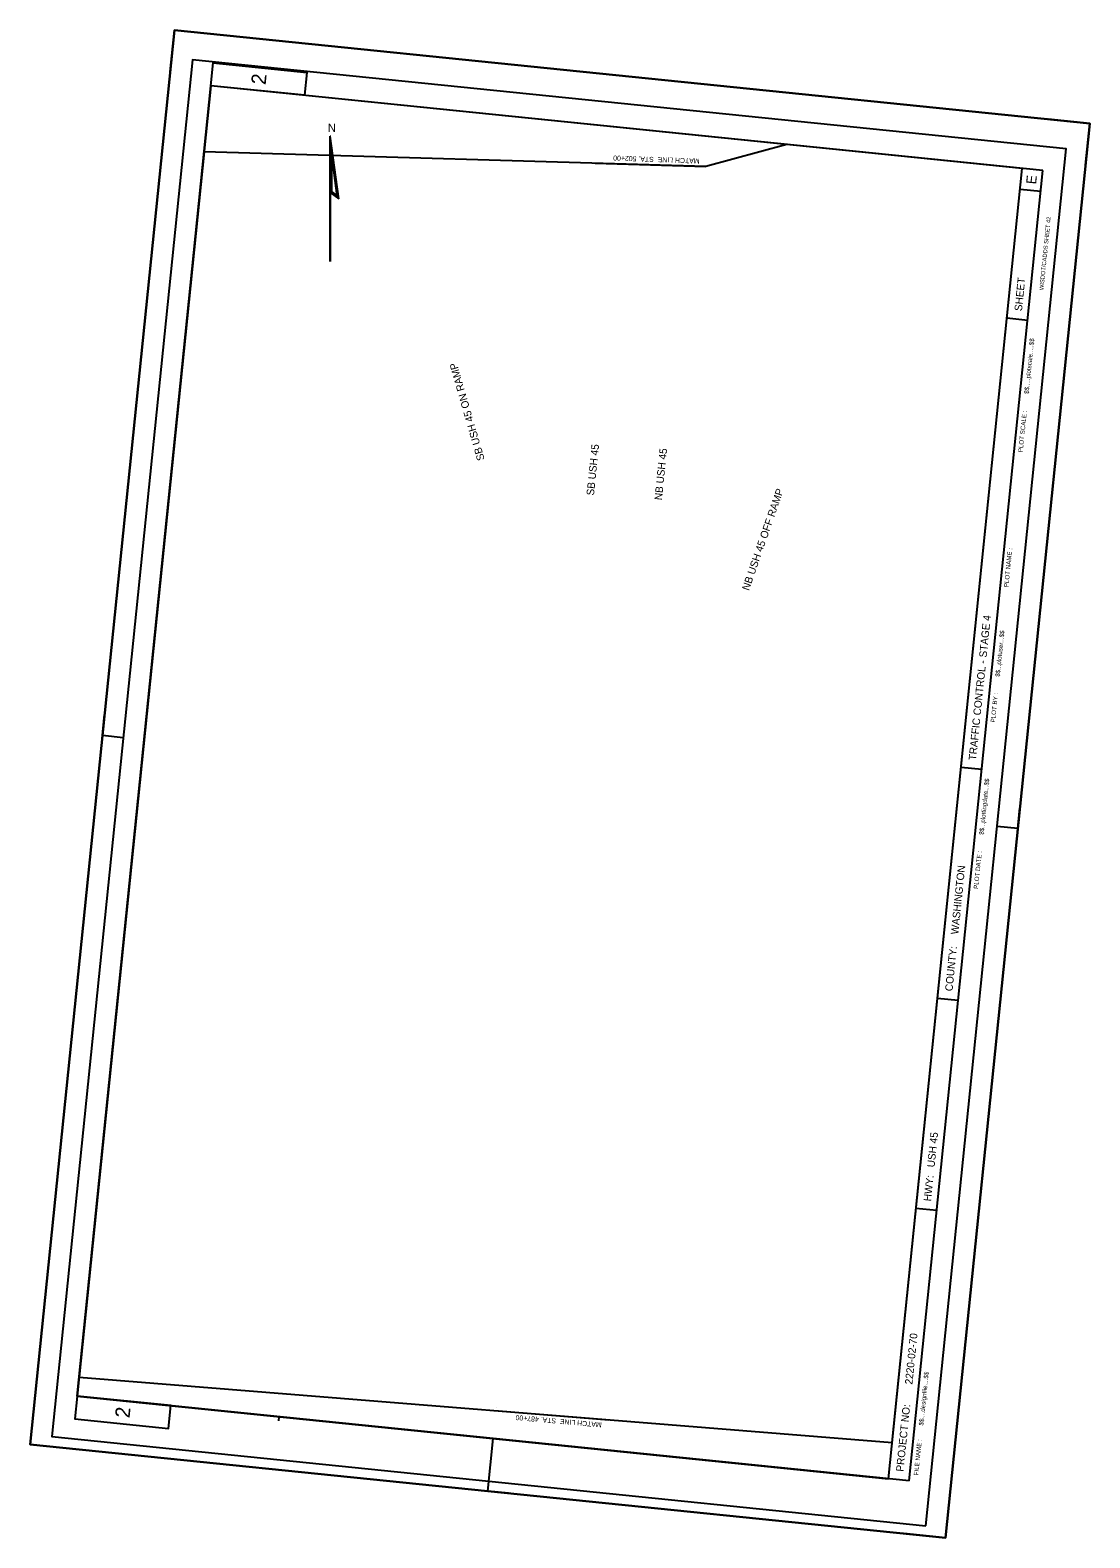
# Model space of a CAD drawing. Extents: x 359372 to 360639, y 172894 to 174697.
import ezdxf

# ---------------------------------------------------------------- set-up
doc = ezdxf.new("R2010")
doc.units = 0
for name, color, linetype in [('Default', 7, 'Continuous'), ('P_ALI_100_Equation', 7, 'Continuous'), ('P_ALI_100_PIData', 7, 'Continuous'), ('P_ALI_20', 7, 'Continuous'), ('P_ALI_200_Equation', 7, 'Continuous'), ('P_ALI_20_Sta', 7, 'Continuous'), ('P_ALI_20_Tic', 7, 'Continuous'), ('P_ALI_50_Equation', 7, 'Continuous'), ('P_ALI_50_Sta', 7, 'Continuous')]:
    doc.layers.add(name, color=color, linetype=linetype)

msp = doc.modelspace()

# ---------------------------------------------------------------- linework, layer by layer
for p, q in [((359539.1, 174647.6), (359544.2, 174697.3)), ((359594, 174692.2), (359544.2, 174697.3)), ((359427.8, 173063.9), (359587.7, 174630.8)), ((360582.5, 174529.3), (359587.7, 174630.8)), ((360638.5, 174585.6), (360588.8, 174590.7)), ((360633.5, 174535.9), (360638.5, 174585.6)), ((360397.7, 172964.9), (360557.7, 174531.8)), ((360422.6, 172962.4), (360582.5, 174529.3)), ((360580, 174504.4), (360555.1, 174506.9)), ((360564.3, 174350.2), (360539.4, 174352.7)), ((359455.6, 173829.3), (359460.7, 173879)), ((359458.2, 173854.2), (359483, 173851.6)), ((360509.4, 173813), (360484.6, 173815.5)), ((360550, 173717.6), (360555, 173767.4)), ((360552.5, 173742.5), (360527.6, 173745)), ((360481.3, 173536.9), (360456.4, 173539.5)), ((360455.6, 173285.7), (360430.7, 173288.3)), ((360422.6, 172962.4), (359427.8, 173063.9)), ((359371.6, 173006.1), (359376.7, 173055.8)), ((359929, 173050.5), (359929, 173050.5)), ((359669, 173039.3), (359668.5, 173034.3)), ((359421.4, 173001), (359371.6, 173006.1)), ((359918.8, 172950.2), (359925.2, 173013.2)), ((359943.7, 172947.7), (359893.9, 172952.8)), ((360465.9, 172894.4), (360471, 172944.1)), ((360465.9, 172894.4), (360416.2, 172899.5))]:
    msp.add_line(p, q)
for points in [[(359587.7, 174630.8), (359590.5, 174658.2), (359702.4, 174646.7), (359699.6, 174619.4)], [(359427.8, 173063.9), (359425, 173036.6), (359536.9, 173025.2), (359539.7, 173052.5)]]:
    msp.add_lwpolyline(points, close=True)
at = {"layer": 'Default'}
msp.add_lwpolyline([(359430.1, 173086.6), (360402.2, 173008.3), (360557.7, 174531.8), (360276.1, 174560.5), (360179.3, 174534.4), (359579.6, 174551.9)], close=True, dxfattribs=at)
msp.add_lwpolyline([(359430.1, 173086.6), (360402.2, 173008.3), (360557.7, 174531.8), (360276.1, 174560.5), (360179.3, 174534.4), (359579.6, 174551.9)], close=True, dxfattribs=at)
at = {"layer": 'P_ALI_100_Equation'}
for p, q in [((359740.6, 174495.7), (359730.5, 174570.7)), ((359730.5, 174503.2), (359730.5, 174570.7)), ((359731.3, 174503.5), (359731.3, 174559.4)), ((359739.6, 174497.3), (359731.3, 174559.4)), ((359732.1, 174503.9), (359732.1, 174548.1)), ((359738.6, 174499), (359732.1, 174548.1)), ((359730.5, 174503.2), (359740.6, 174495.7)), ((359730.5, 174420.7), (359730.5, 174503.2)), ((359730.8, 174420.7), (359730.8, 174503)), ((359731.3, 174503.5), (359739.6, 174497.3)), ((359732.1, 174503.9), (359738.6, 174499))]:
    msp.add_line(p, q, dxfattribs=at)
msp.add_lwpolyline([(359730.6, 174570.6), (359730.5, 174570.6)], dxfattribs=at)
at = {"layer": 'P_ALI_100_PIData'}
msp.add_lwpolyline([(359430.1, 173086.6), (360402.2, 173008.3), (360557.7, 174531.8), (360276.1, 174560.5), (360179.3, 174534.4), (359579.6, 174551.9)], close=True, dxfattribs=at)
at = {"layer": 'P_ALI_20'}
for points in [[(360465.9, 172894.4), (360638.5, 174585.6), (359544.2, 174697.3), (359371.6, 173006.1)], [(360442.3, 172908.9), (360610.3, 174555.3), (359565.7, 174661.9), (359397.7, 173015.5)]]:
    msp.add_lwpolyline(points, close=True, dxfattribs=at)
at = {"layer": 'P_ALI_200_Equation'}
msp.add_lwpolyline([(359371.6, 173006.1), (359544.2, 174697.3), (360638.5, 174585.6), (360465.9, 172894.4), (359371.6, 173006.1)], dxfattribs=at)
at = {"layer": 'P_ALI_20_Sta'}
msp.add_lwpolyline([(359371.6, 173006.1), (359544.2, 174697.3), (360638.5, 174585.6), (360465.9, 172894.4)], close=True, dxfattribs=at)
at = {"layer": 'P_ALI_20_Tic'}
for p, q in [((360047, 174538.3), (360179.3, 174534.4)), ((359931.7, 173046.2), (360063.6, 173035.6))]:
    msp.add_line(p, q, dxfattribs=at)
at = {"layer": 'P_ALI_50_Sta'}
msp.add_lwpolyline([(360557.7, 174531.8), (359587.7, 174630.8), (359427.8, 173063.9), (360397.7, 172964.9)], dxfattribs=at)

# ---------------------------------------------------------------- texts
for s, height, p in [('2', 17.5, (359653.1, 174631.4)), ('E', 12, (360574.2, 174512.6)), ('WISDOT/CADDS SHEET 42', 5, (360583, 174386.2)), ('SHEET ', 9, (360557.3, 174361)), ('$$.....plotscale.....$$', 5.4, (360565.3, 174262.1)), ('PLOT SCALE : ', 5.4, (360558.2, 174192.3)), ('PLOT NAME :                      ', 5.4, (360541.2, 174030.9)), ('TRAFFIC CONTROL - STAGE 4', 9, (360502.5, 173823.7)), ('$$...plotuser...$$', 5.4, (360530.8, 173923.9)), ('PLOT BY :', 5.4, (360525.2, 173869.2)), ('$$...plottingdate...$$', 5.4, (360511.5, 173734.9)), ('PLOT DATE :', 5.4, (360504.9, 173670.2)), (' WASHINGTON', 9, (360480.9, 173612.3)), ('COUNTY:', 9, (360474.3, 173547.7)), (' USH 45', 9, (360452.5, 173333.8)), ('HWY:', 9, (360448.7, 173296.5)), (' 2220-02-70', 9, (360426, 173074.1)), ('$$....designfile....$$', 5.4, (360439.4, 173028.5)), ('2', 17.5, (359490.4, 173037.1)), ('PROJECT NO:', 9, (360415.7, 172973.2)), ('FILE NAME :', 5.4, (360433.3, 172968.9))]:
    msp.add_text(s, height=height, rotation=84.1728).set_placement(p)
at = {"layer": 'P_ALI_100_Equation'}
msp.add_text('N', height=10, dxfattribs=at).set_placement((359727.5, 174575.6))
at = {"layer": 'P_ALI_50_Equation'}
for s, height, rotation, p in [('MATCH LINE  STA. 502+00', 6, 177.9165, (360172.1, 174543.7)), ('SB USH 45 ON RAMP', 9, 106.0772, (359915.1, 174184)), ('SB USH 45', 9, 84.1728, (360045.6, 174140.5)), ('NB USH 45', 9, 84.1728, (360126.9, 174134.9)), ('NB USH 45 OFF RAMP', 9, 70.9446, (360230.9, 174026.5)), ('MATCH LINE  STA. 487+00', 6, 174.9815, (360055.2, 173032.3))]:
    msp.add_text(s, height=height, rotation=rotation, dxfattribs=at).set_placement(p)

doc.saveas('drawing.dxf')
